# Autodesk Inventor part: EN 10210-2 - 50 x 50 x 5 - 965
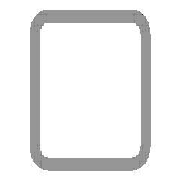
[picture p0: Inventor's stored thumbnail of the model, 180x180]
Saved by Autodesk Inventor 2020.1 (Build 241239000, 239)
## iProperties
_CCFamilyMember: 16
_CCFamilyDisplayName: DIN EN 10210-2 (USAS B17.1 quadratisch) - Rohrleitung — In Klammern angegebene Größen wurden aufgehoben
_FrameMemberDoc: Frame Member File
_Version: 15.0.0
_GetPNFromCC: 1
IsCustomPart: 1
Created: 2019-10
Part Number: EN 10210-2 - 50 x 50 x 5 - 965
Material: Stahl, weich
Description: Rohrleitung
Document SubType Name: Modeling
Standard: DIN
Designer: lutzd
Standard Revision: 2006-07
Standards Organization: DIN
Language: de-DE
Size Designation: 50 x 50 x 5
Categories: <MemberInstance><Categories><Category DisplayName="Profile" InternalName="089c4875-fa83-4c05-b084-43b9cc11f5ed" Mnemonic="GRDR"><CategoryParameter DisplayName="
Stock Number: 50 x 50 x 5
Mass: 6614.52 g
Surface Area: 3284.37 cm^2
Volume: 842.614 cm^3
Density: 7.85 g/cm^3
Appearance: Halbpoliert
G_L: 965,000 mm
G_W: 50,000 mm
G_H: 50,000 mm
Dimensions: 50x50x965 mm
Mass: 6,615 kg
DocNumber: ADSK-014102
Folder: .
+D8A72F49-B87E-4025-A3F3-495C664285AF+SCHNITTDETAIL1: Schnittwinkel 90,00 grd
Title: Profil-Bauteil
Author: lutzd
Revision Number: -
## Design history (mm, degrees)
node "Startebene"
node "Endebene"
sketch "Skizze"
  geometry: L1 (-25, -17.5)-(-25, 17.5); L2 (-17.5, 25)-(17.5, 25); L3 (25, 17.5)-(25, -17.5); L4 (17.5, -25)-(-17.5, -25); L5 (-15, 20)-(15, 20); L6 (20, 15)-(20, -15); L7 (15, -20)-(-15, -20); L8 (-20, -15)-(-20, 15); L9 (0, 37.175)-(0, -37.175) reference; L10 (-37.175, 0)-(37.175, 0) reference; A1 r 7.5 centre (-17.5, -17.5) between (-25, -17.5) and (-17.5, -25); A2 r 7.5 centre (-17.5, 17.5) between (-17.5, 25) and (-25, 17.5); A3 r 7.5 centre (17.5, 17.5) between (25, 17.5) and (17.5, 25); A4 r 7.5 centre (17.5, -17.5) between (17.5, -25) and (25, -17.5); A5 r 5 centre (-15, -15) between (-20, -15) and (-15, -20); A6 r 5 centre (-15, 15) between (-15, 20) and (-20, 15); A7 r 5 centre (15, 15) between (20, 15) and (15, 20); A8 r 5 centre (15, -15) between (15, -20) and (20, -15)
  constraints: 16 end point, 16 point on circle, 16 tangent, 8 centre point, 6 equal radius, 4 parallel, 2 perpendicular, 2 other
  dimensions: "d7" = 7.5 radius of A1 (= G_IR); "d10" = 50 distance between parallel lines of L2 L4 (= G_H); "d11" = 50 distance between parallel lines of L1 L3 (= G_W); "d12" = 5 distance between parallel lines of L3 L6 (= G_T); "d15" = 25 distance between parallel lines of L2 L10 (= 0.5 x d10); "d16" = 25 distance between parallel lines of L9 L3 (= 0.5 x d11); "d19" = 5 radius of A5 (= G_T); "d20" = 5 distance between parallel lines of L4 L7 (= G_T)
extrude "Körper" new body sketch "Skizze" stored distance "d3" = 965 (= G_L); taper "d4" = 0 deg
node "Driven Length"
  sketch "Sketch3"
    geometry: L1 (0, 0)-(10, 0) reference
    constraints: 2 end point, 1 horizontal
  workplane "Work Plane3"
  sketch "Sketch4"
    geometry: L1 (-2, 35)-(12, 35) reference; L2 (-2, 1000)-(12, 1000) reference
    dimensions: "d18" = 965 distance between parallel lines of L1 L2 (derived)
workplane "Arbeitsebene4"
feature "Trennen1"
body "Solid1"
other parameters: "G_W" = 50 [user parameter; used in 1 equation term], "G_H" = 50 [user parameter; used in 1 equation term], "G_T" = 5 [user parameter; used in 3 equation terms], "G_IR" = 7.5 [user parameter; used in 1 equation term], "G_L" = 965 (= d18) [user parameter; used in 1 equation term], "G_OFFSET_START" = -35 [user parameter; used in 1 equation term], "d13" = 35 (= -G_OFFSET_START), "d17" = 90 deg
